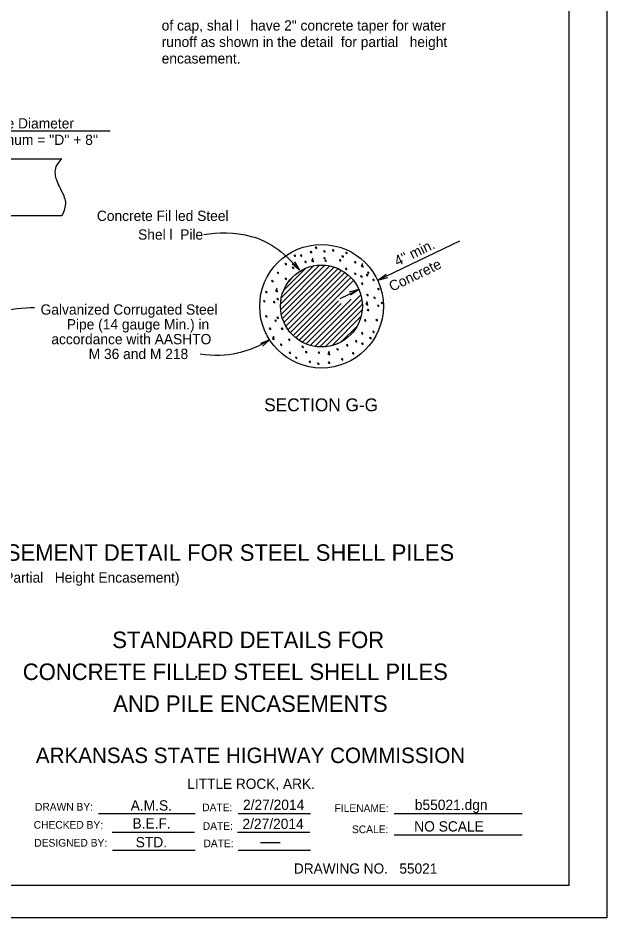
# Model space of a CAD drawing. Extents: x 1053 to 1311, y 5085 to 5337.
# Drawn here: x 1193.9 to 1232, y 5085.1 to 5143.4 of the extents above; entities that cross this region are included whole.
import ezdxf

# ---------------------------------------------------------------- set-up
doc = ezdxf.new("R2010")
doc.units = 0
for name, color, linetype in [('1', 7, 'Continuous'), ('2', 7, 'Continuous'), ('7', 7, 'Continuous'), ('9', 7, 'Continuous'), ('B_No_Plot', 7, 'Continuous')]:
    doc.layers.add(name, color=color, linetype=linetype)

msp = doc.modelspace()

# ---------------------------------------------------------------- linework, layer by layer
at = {"layer": '1'}
for p, q in [((1229.529, 5087.179), (1229.529, 5196.747)), ((1183.514, 5134.241), (1196.697, 5134.241)), ((1183.514, 5130.568), (1196.697, 5130.568)), ((1217.131, 5126.365), (1222.442, 5128.918)), ((1210.846, 5124.823), (1213.369, 5127.346)), ((1210.852, 5124.475), (1213.717, 5127.341)), ((1210.893, 5125.224), (1212.969, 5127.299)), ((1210.895, 5124.165), (1214.027, 5127.297)), ((1210.969, 5123.885), (1214.308, 5127.224)), ((1211.053, 5125.737), (1212.456, 5127.14)), ((1211.066, 5123.629), (1214.563, 5127.126)), ((1211.185, 5123.394), (1214.798, 5127.007)), ((1211.31, 5123.165), (1215.014, 5126.87)), ((1211.503, 5123.005), (1215.213, 5126.715)), ((1217.145, 5126.379), (1217.679, 5126.763)), ((1211.672, 5122.82), (1215.395, 5126.543)), ((1211.838, 5122.633), (1215.56, 5126.355)), ((1217.145, 5126.379), (1217.778, 5126.557)), ((1214.702, 5125.197), (1215.914, 5125.78)), ((1215.914, 5125.78), (1215.281, 5125.602)), ((1215.914, 5125.78), (1215.38, 5125.396)), ((1212.043, 5122.484), (1214.601, 5125.043)), ((1212.265, 5122.353), (1214.778, 5124.866)), ((1212.507, 5122.242), (1215.409, 5125.144)), ((1212.771, 5122.152), (1216.041, 5125.421)), ((1213.06, 5122.088), (1216.105, 5125.132)), ((1213.381, 5122.055), (1216.138, 5124.812)), ((1213.742, 5122.062), (1216.131, 5124.451)), ((1214.176, 5122.142), (1216.05, 5124.017)), ((1214.763, 5122.376), (1215.816, 5123.429)), ((1199.054, 5091.835), (1205.326, 5091.835)), ((1208.105, 5091.835), (1212.772, 5091.835)), ((1218.206, 5091.835), (1226.484, 5091.835)), ((1199.94, 5090.63), (1205.273, 5090.63)), ((1208.062, 5090.63), (1212.729, 5090.63)), ((1218.206, 5090.465), (1226.484, 5090.465)), ((1199.977, 5089.462), (1205.31, 5089.462)), ((1208.105, 5089.462), (1212.772, 5089.462)), ((1229.529, 5087.179), (1060.921, 5087.179))]:
    msp.add_line(p, q, dxfattribs=at)
for points in [[(1212.939, 5127.792), (1212.845, 5127.623), (1212.977, 5127.566), (1212.939, 5127.754)], [(1211.753, 5127.567), (1212.07, 5127.029), (1211.588, 5127.426)], [(1212.987, 5127.304), (1212.975, 5127.29)], [(1214.017, 5127.3), (1214.009, 5127.29)], [(1216.155, 5127.453), (1216.061, 5127.284), (1216.193, 5127.228), (1216.155, 5127.416)], [(1214.806, 5127.004), (1214.784, 5126.978)], [(1211.424, 5126.354), (1211.353, 5126.268)], [(1211.556, 5126.513), (1211.424, 5126.354)], [(1215.563, 5126.357), (1215.56, 5126.354)], [(1210.607, 5125.855), (1210.513, 5125.685), (1210.645, 5125.629), (1210.607, 5125.817)], [(1210.907, 5125.106), (1210.863, 5125.053)], [(1216.107, 5125.142), (1216.077, 5125.106)], [(1216.456, 5124.99), (1216.362, 5124.82), (1216.494, 5124.764), (1216.456, 5124.952)], [(1210.907, 5124.17), (1210.896, 5124.157)], [(1216.094, 5124.191), (1216.077, 5124.17)], [(1210.4, 5122.752), (1210.306, 5122.582), (1210.438, 5122.526), (1210.4, 5122.714)], [(1215.043, 5122.61), (1214.928, 5122.472)], [(1209.558, 5122.29), (1210.139, 5122.522), (1209.672, 5122.106)], [(1212.458, 5122.298), (1212.434, 5122.269)], [(1214.526, 5122.298), (1214.476, 5122.238)], [(1213.992, 5121.773), (1213.898, 5121.604), (1214.03, 5121.548), (1213.992, 5121.736)]]:
    msp.add_lwpolyline(points, dxfattribs=at)
for centre, radius in [((1213.497, 5124.686), 4.003), ((1213.492, 5124.701), 2.652)]:
    msp.add_circle(centre, radius, dxfattribs=at)
for points in [[(1196.697, 5134.241), (1196.306, 5133.738), (1196.25, 5133.235), (1196.334, 5132.872), (1196.529, 5132.425), (1196.808, 5131.838), (1196.92, 5131.419), (1196.697, 5130.568)], [(1213.127, 5128.526), (1213.09, 5128.488), (1213.184, 5128.432), (1213.146, 5128.526)], [(1211.754, 5128.018), (1211.717, 5127.98), (1211.811, 5127.924), (1211.773, 5128.018)], [(1212.168, 5128.018), (1212.131, 5127.98), (1212.225, 5127.924), (1212.187, 5128.018)], [(1212.808, 5128.243), (1212.77, 5128.206), (1212.864, 5128.149), (1212.826, 5128.243)], [(1213.673, 5128.3), (1213.635, 5128.262), (1213.729, 5128.206), (1213.692, 5128.3)], [(1213.673, 5127.848), (1213.635, 5127.811), (1213.729, 5127.754), (1213.692, 5127.848)], [(1214.237, 5128.356), (1214.199, 5128.319), (1214.293, 5128.262), (1214.256, 5128.356)], [(1214.858, 5127.961), (1214.82, 5127.924), (1214.914, 5127.867), (1214.876, 5127.961)], [(1215.102, 5128.187), (1215.065, 5128.149), (1215.159, 5128.093), (1215.121, 5128.187)], [(1211.171, 5127.472), (1211.134, 5127.435), (1211.228, 5127.378), (1211.19, 5127.472)], [(1211.641, 5127.228), (1211.604, 5127.19), (1211.698, 5127.134), (1211.66, 5127.228)], [(1212.45, 5127.604), (1212.413, 5127.566), (1212.507, 5127.51), (1212.469, 5127.604)], [(1213.748, 5127.679), (1213.71, 5127.642), (1213.804, 5127.585), (1213.767, 5127.679)], [(1214.688, 5127.717), (1214.651, 5127.679), (1214.745, 5127.623), (1214.707, 5127.717)], [(1215.666, 5127.585), (1215.629, 5127.548), (1215.723, 5127.491), (1215.685, 5127.585)], [(1210.666, 5126.901), (1210.628, 5126.863), (1210.722, 5126.807), (1210.685, 5126.901)], [(1215.083, 5127.153), (1215.046, 5127.115), (1215.14, 5127.059), (1215.102, 5127.153)], [(1215.666, 5126.833), (1215.629, 5126.795), (1215.723, 5126.739), (1215.685, 5126.833)], [(1216.061, 5126.664), (1216.024, 5126.626), (1216.118, 5126.57), (1216.08, 5126.664)], [(1216.437, 5126.758), (1216.4, 5126.72), (1216.494, 5126.664), (1216.456, 5126.758)], [(1216.513, 5126.908), (1216.475, 5126.87), (1216.569, 5126.814), (1216.532, 5126.908)], [(1210.306, 5126.363), (1210.269, 5126.325), (1210.363, 5126.269), (1210.325, 5126.363)], [(1211.171, 5126.513), (1211.134, 5126.475), (1211.228, 5126.419), (1211.19, 5126.513)], [(1216.118, 5126.193), (1216.08, 5126.156), (1216.174, 5126.099), (1216.137, 5126.193)], [(1216.851, 5126.438), (1216.814, 5126.4), (1216.908, 5126.344), (1216.87, 5126.438)], [(1209.911, 5125.667), (1209.874, 5125.629), (1209.968, 5125.573), (1209.93, 5125.667)], [(1216.456, 5125.46), (1216.419, 5125.422), (1216.513, 5125.366), (1216.475, 5125.46)], [(1217.171, 5125.855), (1217.133, 5125.817), (1217.227, 5125.761), (1217.19, 5125.855)], [(1209.779, 5125.065), (1209.742, 5125.027), (1209.836, 5124.971), (1209.798, 5125.065)], [(1210.419, 5125.008), (1210.381, 5124.971), (1210.475, 5124.914), (1210.438, 5125.008)], [(1210.645, 5125.197), (1210.607, 5125.159), (1210.701, 5125.103), (1210.663, 5125.197)], [(1216.913, 5125.284), (1216.876, 5125.246), (1216.97, 5125.19), (1216.932, 5125.284)], [(1217.397, 5124.952), (1217.359, 5124.914), (1217.453, 5124.858), (1217.416, 5124.952)], [(1216.494, 5124.501), (1216.456, 5124.463), (1216.55, 5124.407), (1216.513, 5124.501)], [(1217.152, 5124.764), (1217.115, 5124.726), (1217.209, 5124.67), (1217.171, 5124.764)], [(1209.911, 5124.087), (1209.874, 5124.049), (1209.968, 5123.993), (1209.93, 5124.087)], [(1210.513, 5123.805), (1210.475, 5123.767), (1210.569, 5123.711), (1210.532, 5123.805)], [(1210.645, 5123.993), (1210.607, 5123.955), (1210.701, 5123.899), (1210.663, 5123.993)], [(1216.306, 5123.824), (1216.268, 5123.786), (1216.362, 5123.73), (1216.325, 5123.824)], [(1217.058, 5123.842), (1217.021, 5123.805), (1217.115, 5123.748), (1217.077, 5123.842)], [(1210.156, 5123.278), (1210.118, 5123.241), (1210.212, 5123.184), (1210.174, 5123.278)], [(1210.927, 5123.278), (1210.889, 5123.241), (1210.983, 5123.184), (1210.946, 5123.278)], [(1211.399, 5122.567), (1211.361, 5122.53), (1211.455, 5122.473), (1211.418, 5122.567)], [(1216.118, 5122.977), (1216.08, 5122.94), (1216.174, 5122.883), (1216.137, 5122.977)], [(1216.644, 5122.676), (1216.607, 5122.639), (1216.701, 5122.582), (1216.663, 5122.676)], [(1216.851, 5123.071), (1216.814, 5123.034), (1216.908, 5122.977), (1216.87, 5123.071)], [(1210.87, 5122.244), (1210.833, 5122.206), (1210.927, 5122.15), (1210.889, 5122.244)], [(1212.262, 5122.112), (1212.225, 5122.074), (1212.319, 5122.018), (1212.281, 5122.112)], [(1215.147, 5122.201), (1215.11, 5122.163), (1215.204, 5122.107), (1215.166, 5122.201)], [(1215.73, 5122.467), (1215.693, 5122.43), (1215.787, 5122.373), (1215.749, 5122.467)], [(1216.13, 5122.317), (1216.093, 5122.28), (1216.187, 5122.223), (1216.149, 5122.317)], [(1211.435, 5121.717), (1211.397, 5121.679), (1211.491, 5121.623), (1211.453, 5121.717)], [(1211.848, 5121.397), (1211.811, 5121.36), (1211.905, 5121.303), (1211.867, 5121.397)], [(1212.488, 5121.773), (1212.45, 5121.736), (1212.544, 5121.679), (1212.507, 5121.773)], [(1213.315, 5121.736), (1213.278, 5121.698), (1213.372, 5121.642), (1213.334, 5121.736)], [(1214.519, 5121.943), (1214.482, 5121.905), (1214.576, 5121.849), (1214.538, 5121.943)], [(1215.532, 5121.684), (1215.495, 5121.646), (1215.589, 5121.59), (1215.551, 5121.684)], [(1212.732, 5121.134), (1212.695, 5121.096), (1212.789, 5121.04), (1212.751, 5121.134)], [(1213.278, 5121.021), (1213.24, 5120.984), (1213.334, 5120.927), (1213.297, 5121.021)], [(1213.974, 5121.086), (1213.936, 5121.049), (1214.03, 5120.992), (1213.992, 5121.086)], [(1214.824, 5121.297), (1214.786, 5121.26), (1214.88, 5121.203), (1214.843, 5121.297)], [(1205.378, 5100.732), (1205.341, 5100.694), (1205.435, 5100.638), (1205.397, 5100.732)]]:
    msp.add_spline(points, degree=3, dxfattribs=at)
at = {"layer": '2'}
msp.add_line((1199.814, 5136.018), (1190.359, 5136.018), dxfattribs=at)
at = {"layer": '7'}
msp.add_line((1209.553, 5089.97), (1210.817, 5089.97), dxfattribs=at)
for points in [[(1205.882, 5129.328), (1206.754, 5129.499), (1209.04, 5129.523), (1210.976, 5128.308), (1212.07, 5127.029)], [(1194.915, 5124.574), (1194.211, 5124.598), (1192.57, 5124.406), (1191.128, 5123.597), (1190.346, 5122.902)], [(1205.631, 5121.602), (1206.541, 5121.467), (1208.098, 5121.533), (1209.531, 5122.146), (1210.139, 5122.522)]]:
    msp.add_open_spline(points, degree=3, dxfattribs=at)
at = {"layer": 'B_No_Plot'}
msp.add_lwpolyline([(1053.308, 5198.862), (1231.974, 5198.862), (1231.974, 5085.07), (1053.308, 5085.07)], close=True, dxfattribs=at)

# ---------------------------------------------------------------- texts
at = {"layer": '1'}
for s, height, p in [('Concrete Fil led Steel', 0.66667, (1198.956, 5130.211)), ('Shel l  Pile', 0.66667, (1201.622, 5128.999)), ('Galvanized Corrugated Steel', 0.66667, (1195.312, 5124.142)), ('Pipe (14 gauge Min.) in', 0.66667, (1197.007, 5123.184)), ('accordance with AASHTO ', 0.66667, (1196.008, 5122.225)), ('M 36 and M 218', 0.66667, (1198.424, 5121.267)), ('SECTION G-G', 0.83325, (1209.786, 5117.886)), ('ARKANSAS STATE HIGHWAY COMMISSION', 0.99734, (1195.006, 5095.104)), ('LITTLE ROCK, ARK.', 0.66134, (1204.809, 5093.43)), ('DRAWN BY:', 0.496, (1194.948, 5092.022)), ('DATE:', 0.496, (1205.774, 5091.984)), ('FILENAME:', 0.496, (1214.34, 5091.936)), ('b55021.dgn', 0.6667, (1219.535, 5092.066)), ('CHECKED BY:', 0.496, (1194.862, 5090.854)), ('DATE:', 0.496, (1205.812, 5090.779)), ('SCALE:', 0.496, (1215.465, 5090.566)), ('NO SCALE', 0.6667, (1219.495, 5090.67)), ('DESIGNED BY:', 0.496, (1194.905, 5089.691)), ('DATE:', 0.496, (1205.854, 5089.654)), ('DRAWING NO.   55021 ', 0.66134, (1211.707, 5087.944))]:
    msp.add_text(s, height=height, dxfattribs=at).set_placement(p)
for s, rotation, p in [("4'' min.", 25.67294, (1218.407, 5127.263)), ('Concrete', 25.67262, (1218.062, 5125.621))]:
    msp.add_text(s, height=0.6667, rotation=rotation, dxfattribs=at).set_placement(p)
at = {"layer": '7'}
for s, height, p in [('of cap, shal l   have 2" concrete taper for water', 0.66667, (1203.149, 5142.54)), ('runoff as shown in the detail  for partial   height', 0.66667, (1203.149, 5141.473)), ('encasement.', 0.66667, (1203.149, 5140.406)), ('ALTERNATE PILE ENCASEMENT DETAIL FOR STEEL SHELL PILES', 1.067, (1176.807, 5108.201)), ('(Shown with Partial   Height Encasement)', 0.66658, (1187.856, 5106.787)), ('STANDARD DETAILS FOR', 1.067, (1199.952, 5102.55)), ('CONCRETE FILLED STEEL SHELL PILES', 1.067, (1194.159, 5100.483)), ('AND PILE ENCASEMENTS', 1.067, (1200.015, 5098.416)), ('A.M.S.', 0.6667, (1201.143, 5092.029)), ('2/27/2014', 0.6666, (1208.413, 5092.068)), ('B.E.F.', 0.6666, (1201.256, 5090.864)), ('2/27/2014', 0.6666, (1208.377, 5090.833)), ('STD.', 0.6667, (1201.468, 5089.647))]:
    msp.add_text(s, height=height, dxfattribs=at).set_placement(p)
at = {"layer": '9'}
for s, p in [('Inside Diameter', (1191.228, 5136.199)), ("Minimum = ''D'' + 8''", (1191.228, 5135.133))]:
    msp.add_text(s, height=0.66667, dxfattribs=at).set_placement(p)

doc.saveas('drawing.dxf')
